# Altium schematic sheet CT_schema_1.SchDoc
size 447 x 436 mm
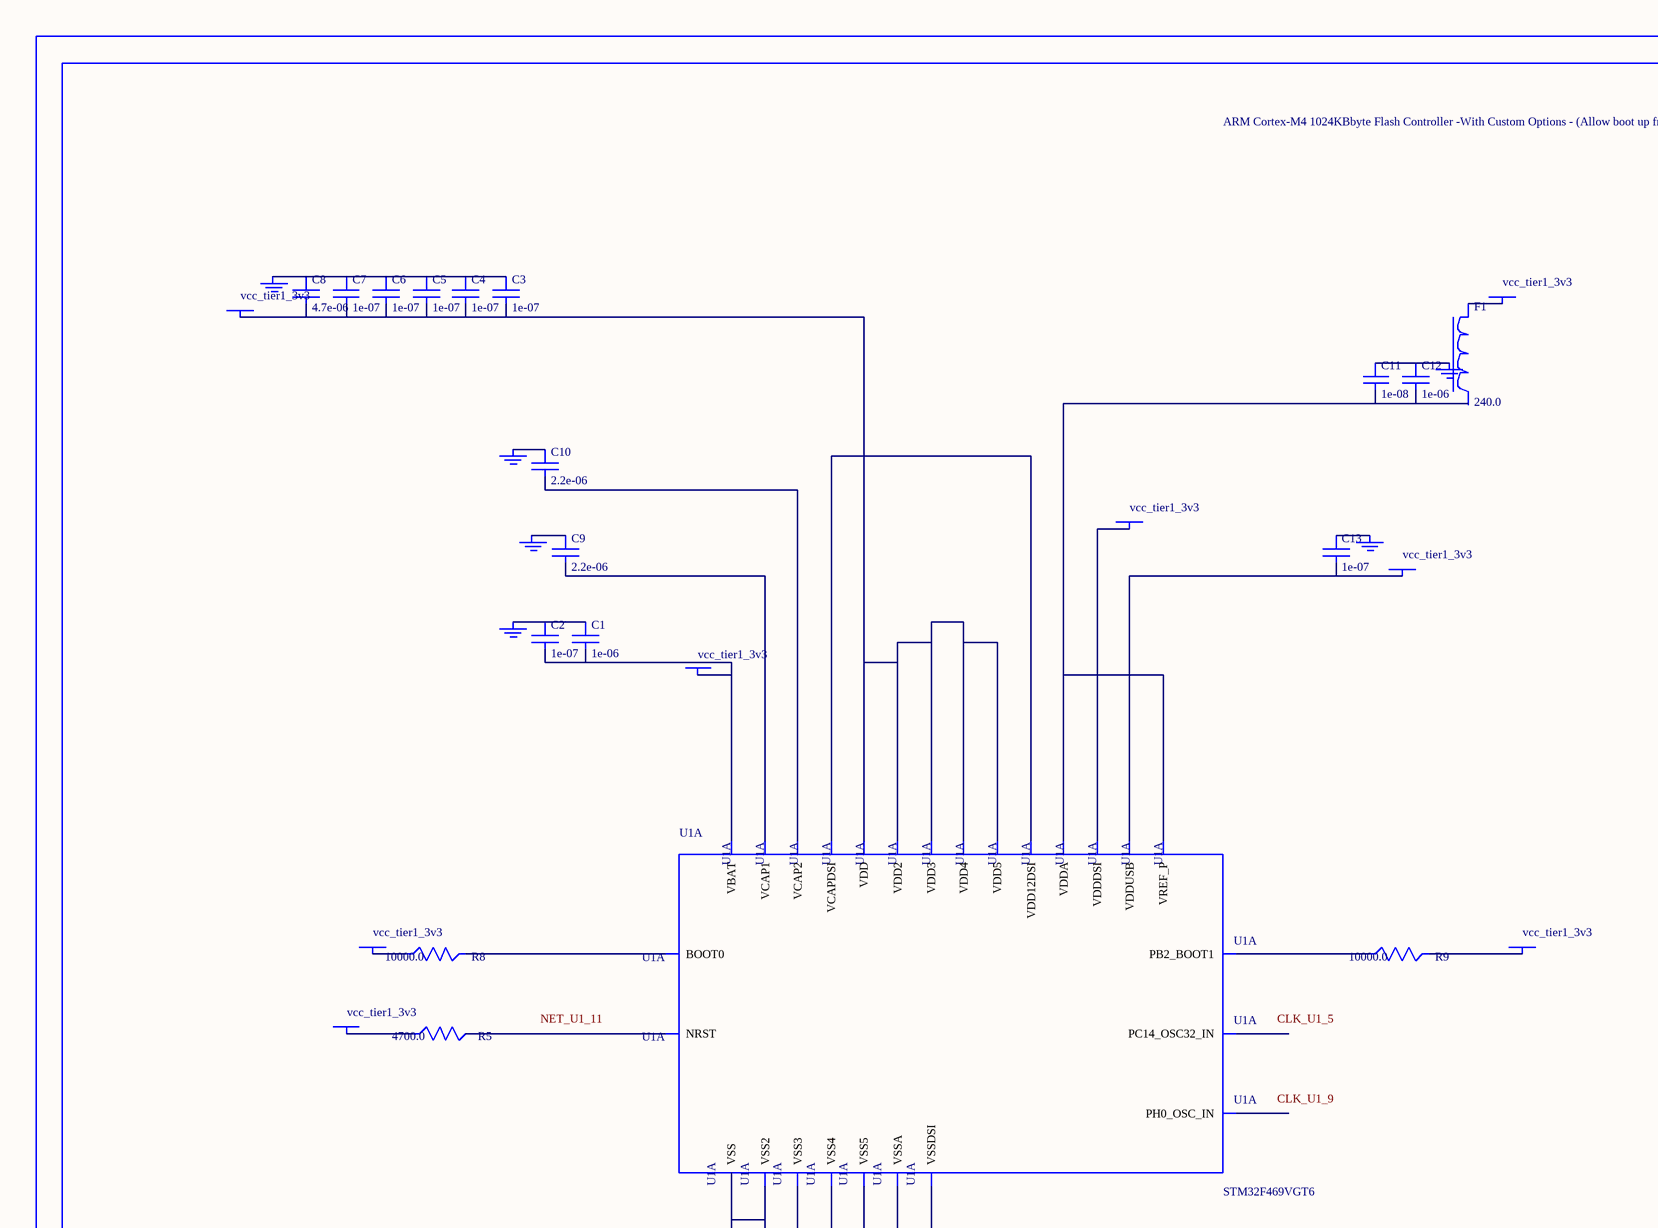
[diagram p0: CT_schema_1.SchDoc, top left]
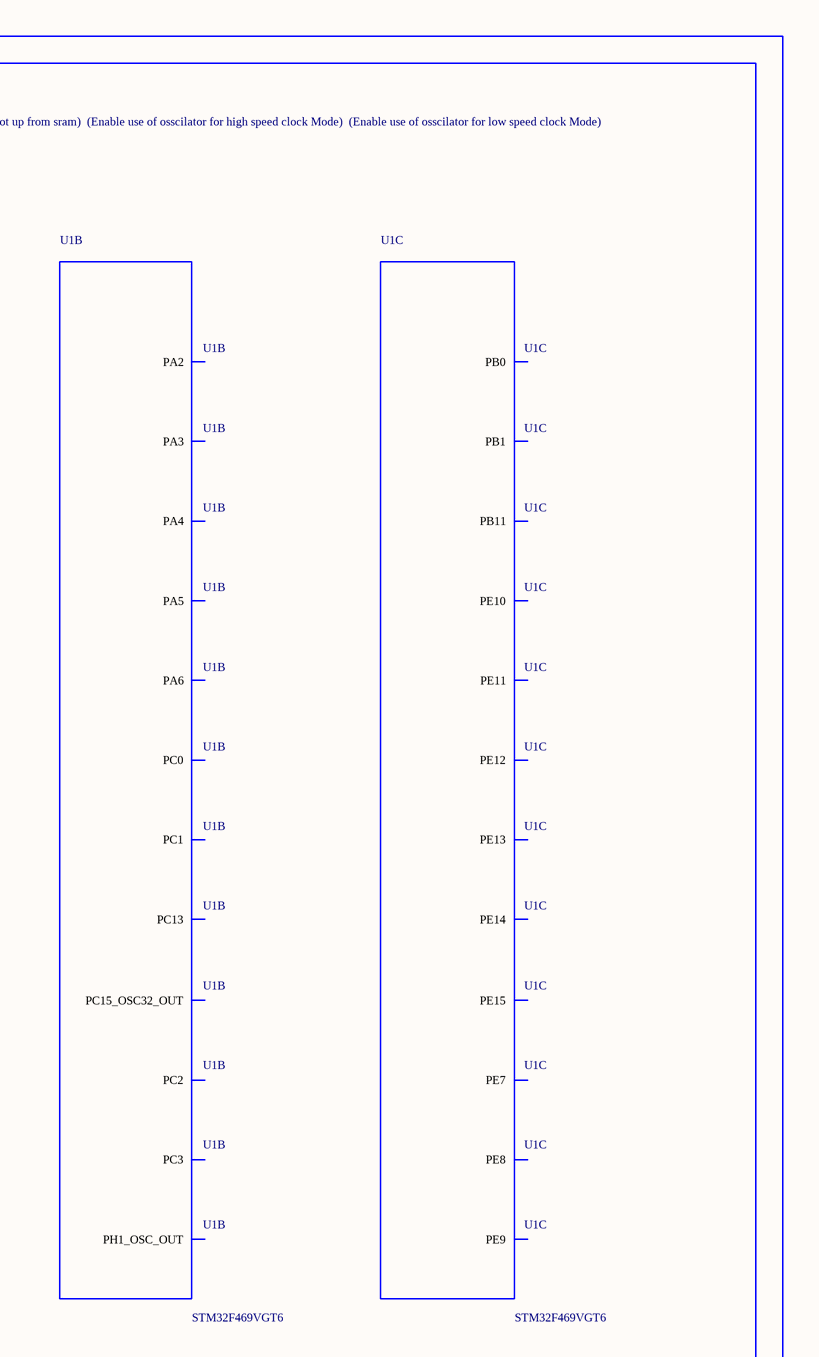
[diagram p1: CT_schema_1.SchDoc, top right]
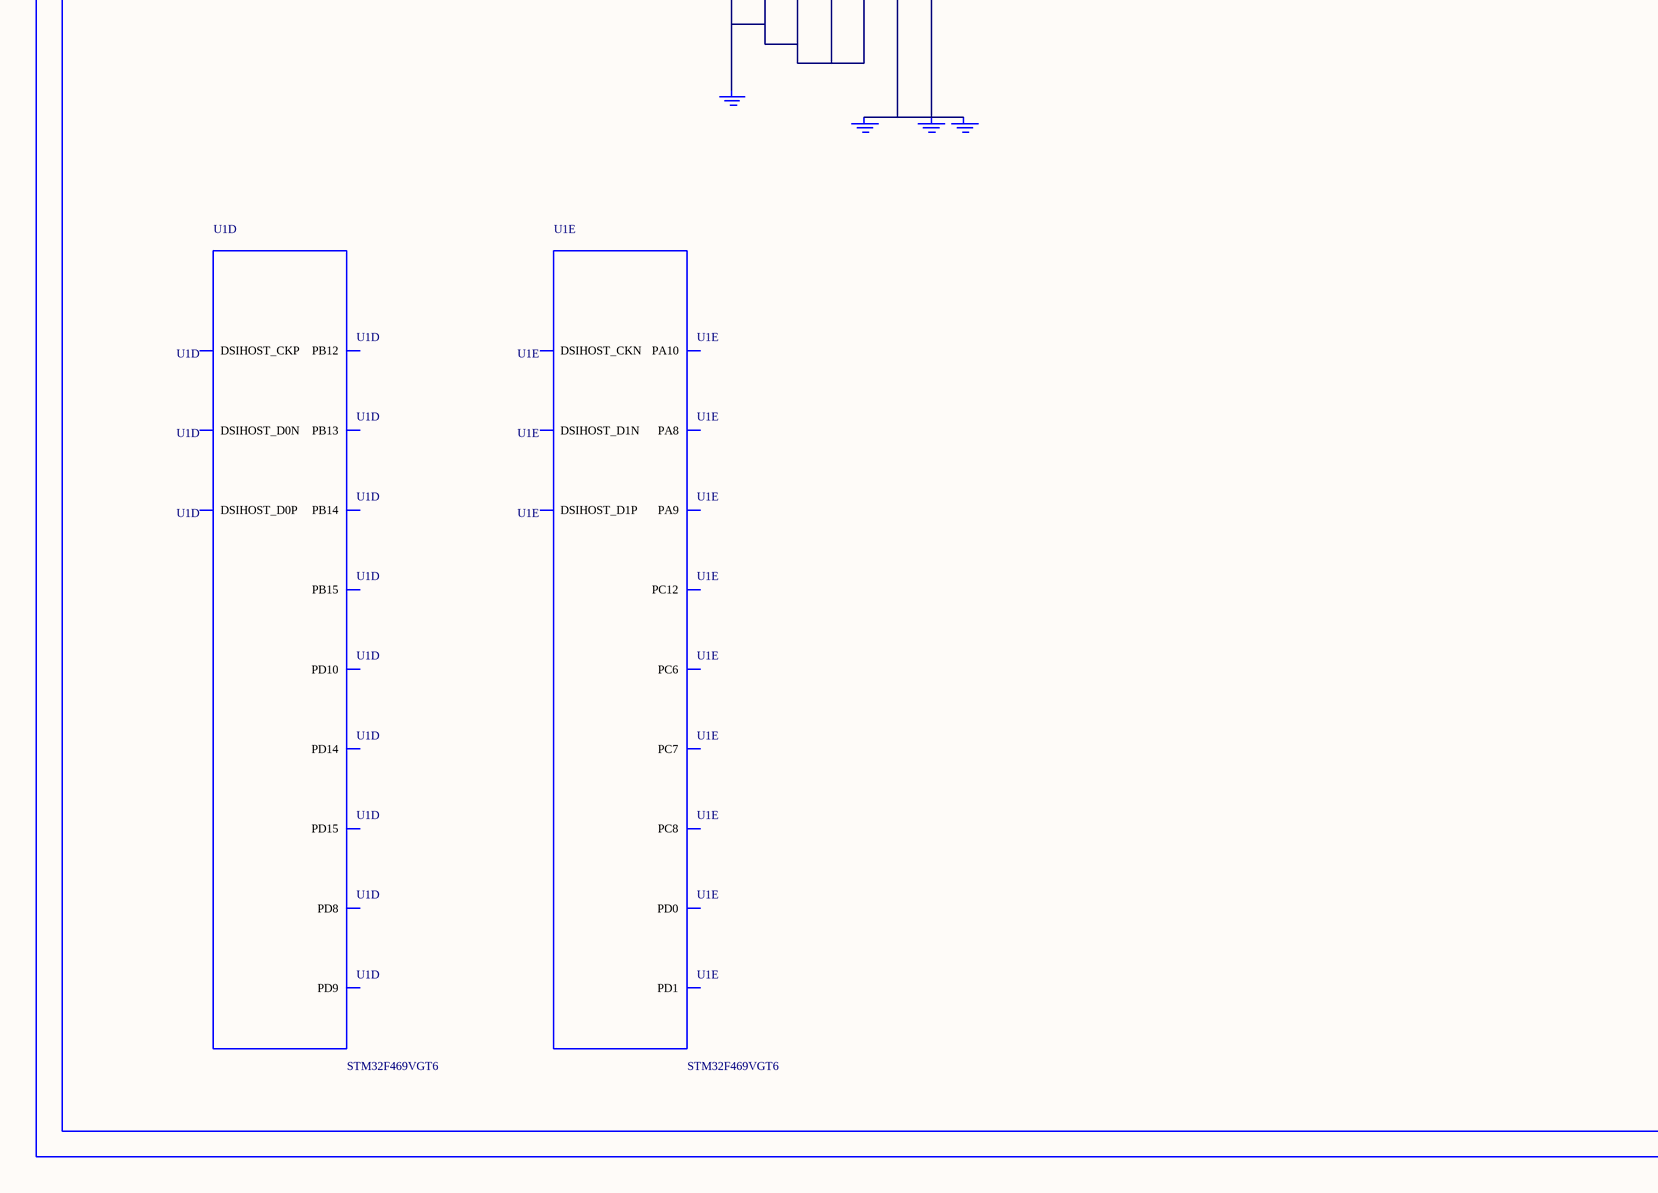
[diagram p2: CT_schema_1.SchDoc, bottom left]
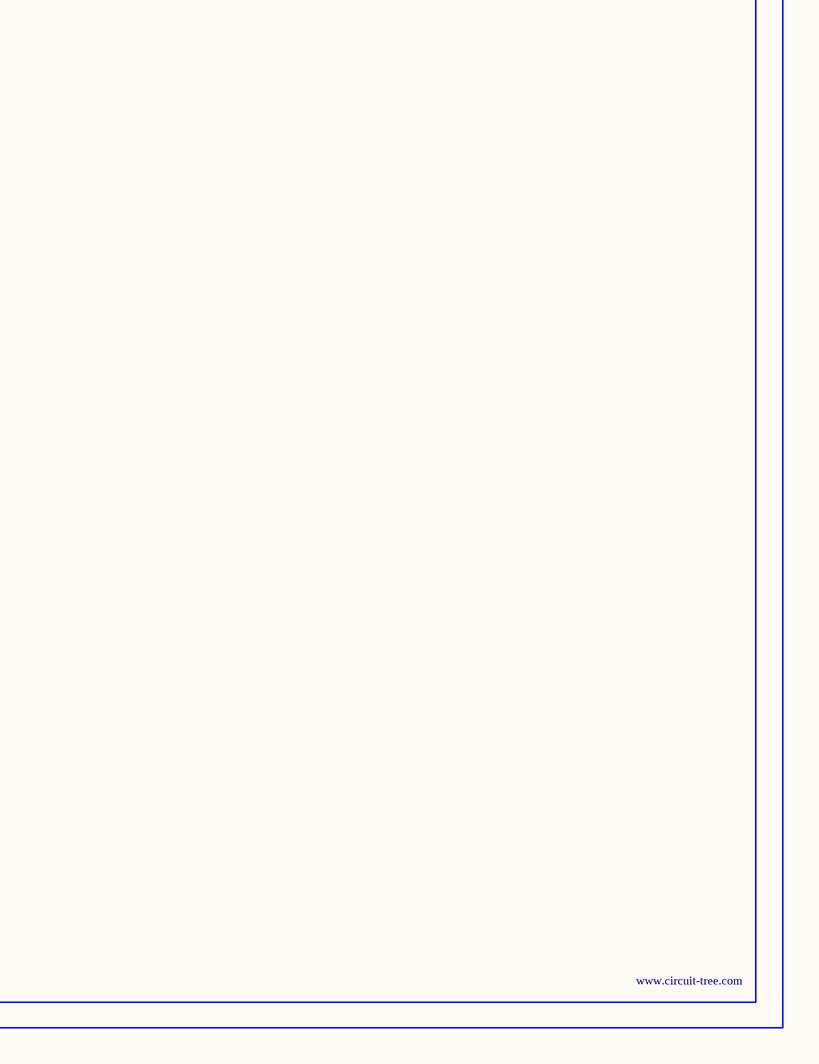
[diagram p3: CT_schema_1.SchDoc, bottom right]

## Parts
BORDER0  (no value)
C1  1e-06  [C0603]
C2  1e-07  [C0603]
C3  1e-07  [C0603]
C4  1e-07  [C0603]
C5  1e-07  [C0603]
C6  1e-07  [C0603]
C7  1e-07  [C0603]
C8  4.7e-06  [C0603]
C9  2.2e-06  [C0603]
C10  2.2e-06  [C0603]
C11  1e-08  [C0603]
C12  1e-06  [C0603]
C13  1e-07  [C0603]
F1  240.0  [L0603]
GND_INSTANCE_0_0  (no value)
GND_INSTANCE_0_1  (no value)
GND_INSTANCE_0_2  (no value)
GND_INSTANCE_0_3  (no value)
GND_INSTANCE_0_4  (no value)
GND_INSTANCE_0_5  (no value)
GND_INSTANCE_0_6  (no value)
GND_INSTANCE_0_7  (no value)
GND_INSTANCE_0_8  (no value)
GND_INSTANCE_0_9  (no value)
POWER_INSTANCE_0_0  vcc_tier1_3v3
POWER_INSTANCE_0_1  vcc_tier1_3v3
POWER_INSTANCE_0_2  vcc_tier1_3v3
POWER_INSTANCE_0_3  vcc_tier1_3v3
POWER_INSTANCE_0_4  vcc_tier1_3v3
POWER_INSTANCE_0_5  vcc_tier1_3v3
POWER_INSTANCE_0_6  vcc_tier1_3v3
POWER_INSTANCE_0_7  vcc_tier1_3v3
R5  4700.0  [R0603]
R8  10000.0  [R0603]
R9  10000.0  [R0603]
U1  STM32F469VGT6  [LQFP100]  (parts A,B,C,D,E of 10)

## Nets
NetC1_1: C1.1 C2.1 GND_INSTANCE_0_0.0(GND)
NetC1_2: C1.2 C2.2 POWER_INSTANCE_0_0.0(PWR) U1.3(VBAT)
NetC3_1: C3.1 C4.1 C5.1 C6.1 C7.1 C8.1 GND_INSTANCE_0_1.0(GND)
NetC3_2: C3.2 C4.2 C5.2 C6.2 C7.2 C8.2 POWER_INSTANCE_0_1.0(PWR) U1.8(VDD) U1.24(VDD2) U1.45(VDD3) U1.77(VDD4) U1.100(VDD5)
NetC9_1: C9.1 GND_INSTANCE_0_4.0(GND)
NetC9_2: C9.2 U1.43(VCAP1)
NetC10_1: C10.1 GND_INSTANCE_0_8.0(GND)
NetC10_2: C10.2 U1.76(VCAP2)
NetC11_1: C11.1 C12.1 GND_INSTANCE_0_3.0(GND)
NetC11_2: C11.2 C12.2 U1.17(VREF_P) U1.18(VDDA)
NetC13_1: C13.1 GND_INSTANCE_0_7.0(GND)
NetC13_2: C13.2 POWER_INSTANCE_0_5.0(PWR) U1.65(VDDUSB)
NetF1_1: F1.1 POWER_INSTANCE_0_2.0(PWR)
NetGND_INSTANCE_0_2_0: GND_INSTANCE_0_2.0(GND) GND_INSTANCE_0_5.0(GND) GND_INSTANCE_0_6.0(GND) U1.16(VSSA) U1.59(VSSDSI)
NetGND_INSTANCE_0_9_0: GND_INSTANCE_0_9.0(GND) U1.2(VSS) U1.7(VSS2) U1.23(VSS3) U1.44(VSS4) U1.78(VSS5)
NetPOWER_INSTANCE_0_3_0: POWER_INSTANCE_0_3.0(PWR) R9.2
NetPOWER_INSTANCE_0_4_0: POWER_INSTANCE_0_4.0(PWR) U1.55(VDDDSI)
NetPOWER_INSTANCE_0_6_0: POWER_INSTANCE_0_6.0(PWR) R8.1
NetPOWER_INSTANCE_0_7_0: POWER_INSTANCE_0_7.0(PWR) R5.1
NetR5_2: R5.2 U1.11(NRST)
NetR8_2: R8.2 U1.97(BOOT0)
NetR9_1: R9.1 U1.31(PB2_BOOT1)
NetU1_56: U1.56(VCAPDSI) U1.62(VDD12DSI)

Not connected (* = marked no-connect by the designer): F1 2; U1 4(PC13) 5(PC14_OSC32_IN) 6(PC15_OSC32_OUT) 9(PH0_OSC_IN) 10(PH1_OSC_OUT) 12(PC0) 13(PC1) 14(PC2) 15(PC3) 21(PA2) 22(PA3) 25(PA4) 26(PA5) 27(PA6) 29(PB0) 30(PB1) 32(PE7) 33(PE8) 34(PE9) 35(PE10) 36(PE11) 37(PE12) 38(PE13) 39(PE14) 40(PE15) 42(PB11) 46(PB12) 47(PB13) 48(PB14) 49(PB15) 50(PD8) 51(PD9) 52(PD10) 53(PD14) 54(PD15) 57(DSIHOST_D0P) 58(DSIHOST_D0N) 60(DSIHOST_CKP) 61(DSIHOST_CKN) 63(DSIHOST_D1P) 64(DSIHOST_D1N) 66(PC6) 67(PC7) 68(PC8) 70(PA8) 71(PA9) 72(PA10) 83(PC12) 84(PD0) 85(PD1)

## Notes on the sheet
- Labels drawn without touching a wire or pin: CLK_U1_5, CLK_U1_9, NET_U1_11

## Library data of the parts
BORDER0 = BORDER_PAGE0
C1 C12 = C0603C105K3RACTU
C2-C7 C13 = 06035C104K4Z2A
C8 = GRM188R6YA475KE15D
C9 C10 = C0603C225K8RACTU
C11 = 06035C103K4Z2A
F1 = Z0603C241ASMST
GND_INSTANCE_0_0-GND_INSTANCE_0_9 = GND
POWER_INSTANCE_0_0-POWER_INSTANCE_0_7 = PWR
R5 = RC0603JR-074K7L
R8 R9 = RC0603JR-0710KL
